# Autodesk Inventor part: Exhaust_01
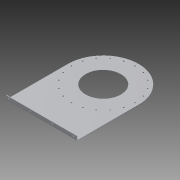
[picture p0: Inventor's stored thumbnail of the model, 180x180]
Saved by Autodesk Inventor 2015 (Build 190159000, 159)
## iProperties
Created: 2006-05
Part Number: Exhaust_01
Document SubType Name: Sheet Metal
Designer: Autodesk, Inc.
Density: 2.71 g/cm^3
Material: Aluminum-6061
Mass: 1476.17 g
Surface Area: 3662.83 cm^2
Volume: 544.712 cm^3
Sheet Metal Rule: Default
Appearance: Aluminum - Flat
Author: Autodesk, Inc.
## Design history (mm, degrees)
derived "MainGeom.ipt"
  sketch "Sketch1"
    geometry: L1 (0, 300)-(-300, 300) reference; L2 (-300, 0)-(-300, 300) reference; L3 (-200, 0)-(-200, -350) reference; L4 (-200, -350)-(200, -350) reference; L5 (200, -350)-(200, 0) reference; C1 r 100 at (0, 0) reference; A1 r 300 centre (0, 0) between (0, 300) and (-300, 0) reference; A2 r 200 centre (0, 0) between (200, 0) and (-200, 0) reference; 1 further point
node "Face1"
node "Flange1"
sketch "Sketch7"
  geometry: 20 further points
hole "Hole2" sketch "Sketch7" at (0, 180), (-55.623, 171.19), (-105.801, 145.623), (-145.623, 105.801), (-171.19, 55.623), (-180, 0), (-171.19, -55.623), (-145.623, -105.801), (-105.801, -145.623), (-55.623, -171.19), (0, -180), (55.623, -171.19)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 diameter "d32" = 6.7564; stored, may be unused: countersink angle "d36" = 82 deg, drill point angle "d38" = 0 deg; dims "d33" = 12.7, "d34" = 9.525, "d35" = 6.35, "d37" = 19.05
hole "Hole3" diameter "d41" = 6.7564; stored, may be unused: countersink angle "d45" = 82 deg, drill point angle "d47" = 118 deg; dims "d39" = 9.525, "d40" = 19.05, "d42" = 12.7, "d43" = 11.1252, "d44" = 6.35, "d46" = 3.048 (= Thickness)
pattern_linear "Rectangular Pattern1" dims "d50" = 121.92
body "Solid1"
face "Plate1" dims "Thickness" = 3.048
sketch "Sketch6"
  geometry: L1 through (200, 0) direction (-1, 0); L2 through (0, -12.7) direction (0, -1); L3 (0, -25.4)-(400, -25.4); L4 (400, -25.4)-(400, 0)
  constraints: 6 end point, 1 horizontal, 1 perpendicular, 1 vertical
face "Plate2" dims "d23" = 3.048 (= BendReliefWidth), "d24" = 1.524 (= BendReliefDepth), "d25" = 6.096 (= MinimumRemnant), "d26" = 3.048 (= BendRadius), "d27" = 25.4, "d28" = 90 deg, "d29" = 3.048 (= BendRadius), "d30" = 12.192 (= CornerReliefSize), "d31" = 3.048 (= Thickness), "d51" = 3.048 (= JacobiRadiusSize), "SeamGap" = 0.01, "Thickness" = 3.048
bend "Bend1" dims "d23" = 3.048 (= BendReliefWidth), "d24" = 1.524 (= BendReliefDepth), "d25" = 6.096 (= MinimumRemnant), "d26" = 3.048 (= BendRadius), "d27" = 25.4, "d28" = 90 deg, "d29" = 3.048 (= BendRadius), "SeamGap" = 0.01, "Thickness" = 3.048
feature "Corner1" dims "d27" = 25.4, "d28" = 90 deg, "d30" = 12.192 (= CornerReliefSize), "d31" = 3.048 (= Thickness), "d51" = 3.048 (= JacobiRadiusSize)
other parameters: "t" = 3 [user parameter], "BendRadius" = 3.048 (= Thickness), "BendReliefWidth" = 3.048 (= Thickness), "BendReliefDepth" = 1.524 (= 0.5 x Thickness), "CornerReliefSize" = 12.192 (= 4 x Thickness), "MinimumRemnant" = 6.096 (= 2 x Thickness), "TransitionRadius" = 3.048 (= BendRadius), "JacobiRadiusSize" = 3.048 (= Thickness), "d22" = 3.048 (= BendRadius), "GapSize" = 3.048 (= Thickness)
